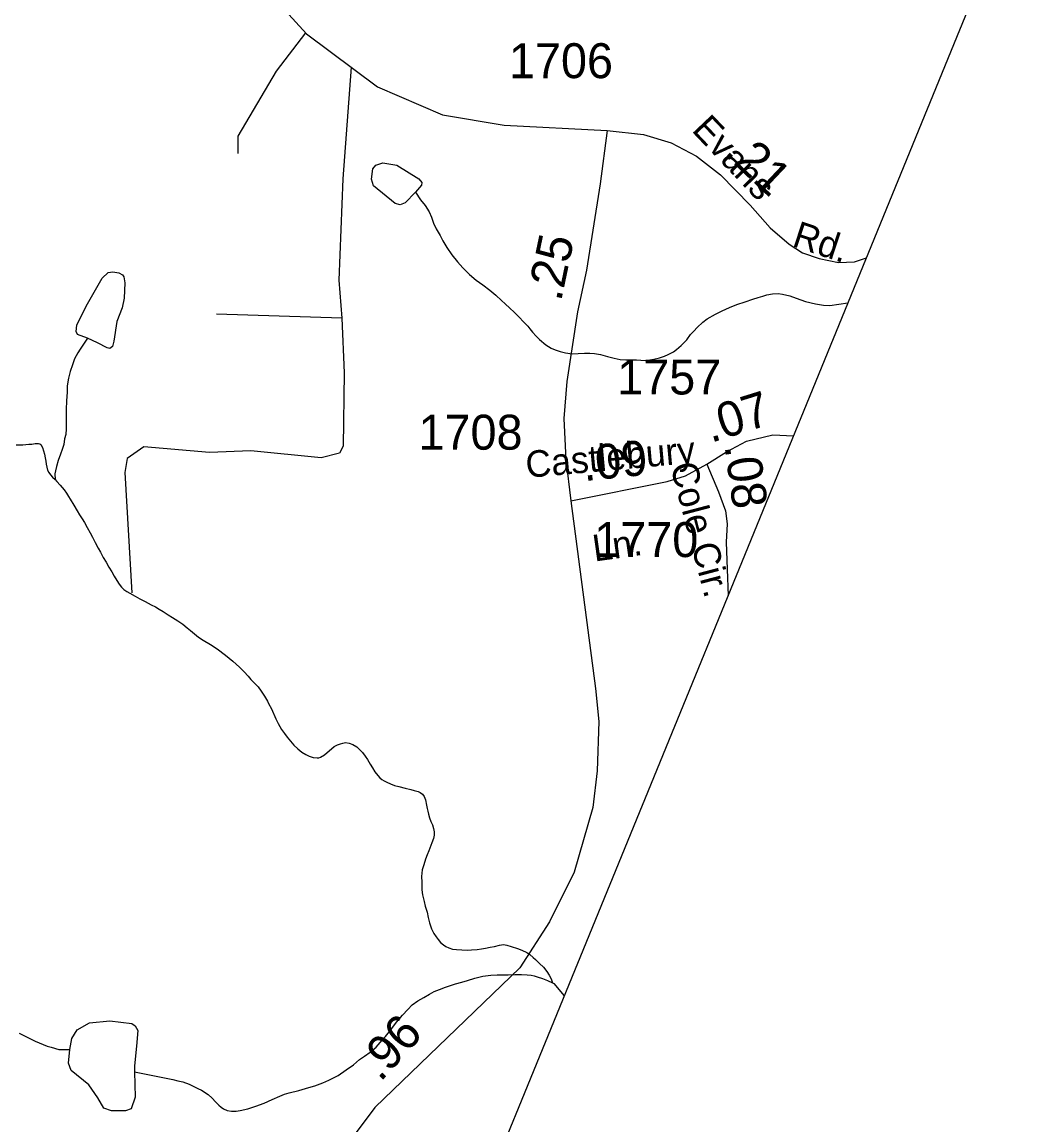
# Model space of a CAD drawing. Extents: x 2056842 to 2160602, y 826753 to 1016856.
# Drawn here: x 2136734 to 2140314, y 858350 to 862292 of the extents above; entities that cross this region are included whole.
import ezdxf

# ---------------------------------------------------------------- set-up
doc = ezdxf.new("R2010")
doc.units = 0
for name, color, linetype in [('Exist Boundary Political CountyLine', 7, 'Continuous'), ('Exist Hydrographic Misc Water Feature', 7, 'Continuous'), ('Exist Road Non-System Type 51', 7, 'Continuous'), ('Exist Road Non-System Type 51 Label', 7, 'Continuous'), ('Exist Road Secondary Mileage Hundredths English Label', 7, 'Continuous'), ('Exist Road Secondary Type 51 Attributed', 7, 'Continuous'), ('Exist Road Secondary Type 51 Label', 7, 'Continuous'), ('Exist Road Secondary Type 51 Number Label', 7, 'Continuous')]:
    doc.layers.add(name, color=color, linetype=linetype)

msp = doc.modelspace()

# ---------------------------------------------------------------- linework, layer by layer
at = {"layer": 'Exist Boundary Political CountyLine'}
msp.add_lwpolyline([(2133839.4, 827270.1), (2134339.4, 835334.3), (2134341.8, 841203.1), (2134508, 848637.7), (2140998.3, 864497.6)], dxfattribs=at)
at = {"layer": 'Exist Hydrographic Misc Water Feature'}
for points in [[(2138139.2, 861683.7), (2138102.5, 861646.3), (2138084.3, 861639), (2138067.3, 861643.9), (2137989.5, 861705.9), (2137982.2, 861730.3), (2137987, 861766.7), (2137998, 861780.1), (2138023.5, 861788.6), (2138073.3, 861780.1), (2138151.1, 861731.5), (2138162.1, 861718.1), (2138160.9, 861708.4), (2138139.2, 861683.7)], [(2138139.2, 861683.7), (2138157.8, 861657), (2138174.7, 861636.1), (2138188.6, 861613.8), (2138196.8, 861593.9), (2138204.4, 861573.3), (2138213.2, 861552.6), (2138227.4, 861528.5), (2138237.6, 861510.2), (2138252, 861486.1), (2138269.8, 861460.4), (2138290.3, 861434.5), (2138308.3, 861412.8), (2138332.5, 861389.3), (2138356.9, 861369.2), (2138380.1, 861352.2), (2138405.1, 861333.7), (2138426.9, 861315.1), (2138446.6, 861296.8), (2138459.5, 861284.2), (2138477.1, 861269.1), (2138491.9, 861254.8), (2138509.9, 861237.2), (2138525.7, 861220.5), (2138540.5, 861205.4), (2138548.5, 861195.5), (2138558.3, 861182.9), (2138570.4, 861169.5), (2138582.7, 861157.8), (2138604.9, 861137.7), (2138624.9, 861125.8), (2138638.9, 861119.7), (2138657.1, 861114.4), (2138675.2, 861110), (2138699.2, 861106.2), (2138721.1, 861106.6), (2138743.1, 861108.5), (2138763.2, 861108.9), (2138779.1, 861107), (2138801.1, 861103.2), (2138826.1, 861096.2), (2138849.1, 861090), (2138871.2, 861086.2), (2138891.1, 861084.1), (2138907.3, 861084.6), (2138929, 861084.1), (2138945.4, 861083), (2138961, 861082.7), (2138977, 861084.9), (2138991.2, 861087), (2139011.1, 861091.5), (2139029.1, 861097.7), (2139042.8, 861103.1), (2139061.1, 861113.5), (2139072.8, 861121.4), (2139088.8, 861135.8), (2139108.7, 861155.9), (2139122.8, 861174.5), (2139134.3, 861187.4), (2139146.4, 861200.3), (2139165.9, 861218.6), (2139181.9, 861230.6), (2139211.8, 861247.4), (2139235.6, 861259.1), (2139261.6, 861271.7), (2139287.5, 861281.8), (2139317.4, 861291.9), (2139344.9, 861301.2), (2139364.2, 861307.3), (2139381.2, 861312.7), (2139395.1, 861316.6), (2139415.2, 861320.1), (2139435.1, 861321.5), (2139451.1, 861319.4), (2139477.1, 861313.2), (2139500.5, 861304.5), (2139533.1, 861293.2), (2139569.4, 861284.2), (2139597.3, 861280.4), (2139619.7, 861279), (2139684.9, 861288.1)], [(2136967.3, 861161.6), (2136931.8, 861174.5), (2136927, 861185.4), (2136929.4, 861208.5), (2136962.2, 861276.6), (2137020.5, 861376.4), (2137041.2, 861397), (2137058.2, 861399.5), (2137080.1, 861395.8), (2137092.3, 861388.5), (2137097.1, 861381.2), (2137100.8, 861359.3), (2137098.3, 861304.6), (2137091, 861270.6), (2137072.8, 861221.9), (2137061.9, 861151.4), (2137057, 861131.9), (2137047.3, 861124.6), (2137037.6, 861127), (2137003.5, 861145.3), (2136967.3, 861161.6)], [(2136967.3, 861161.6), (2136941.1, 861122.8), (2136933.5, 861109), (2136921.4, 861088.7), (2136913.8, 861066.8), (2136905.8, 861042.3), (2136900, 861018.6), (2136895.1, 860991.7), (2136894.7, 860968.8), (2136892.9, 860938.4), (2136891.2, 860906.5), (2136891.4, 860876.1), (2136891.6, 860854), (2136891.6, 860838.4), (2136889.8, 860818), (2136885.9, 860802.5), (2136882.4, 860782), (2136876.5, 860764), (2136870.9, 860746.9), (2136862.9, 860724.2), (2136857, 860703.8), (2136853.1, 860688.3), (2136851, 860677.6), (2136851.5, 860656.3)], [(2136712.4, 860780.6), (2136736.4, 860780.9), (2136758.4, 860782.9), (2136768.4, 860783.5), (2136780.1, 860785), (2136788.1, 860785.6), (2136792.2, 860785.5), (2136797.3, 860784.6), (2136801.2, 860782), (2136806.3, 860771.2), (2136810.4, 860759.7), (2136813.3, 860747.3), (2136816.4, 860734.1), (2136818.6, 860721.8), (2136820.1, 860712), (2136822.3, 860700.4), (2136825.2, 860689.7), (2136829.1, 860681.4), (2136835, 860673.9), (2136843, 860665.5), (2136851.5, 860656.3)], [(2136851.5, 860656.3), (2136857.4, 860649.6), (2136869.3, 860636.3), (2136883.6, 860620.4), (2136893.1, 860607.9), (2136899.8, 860596.2), (2136905.8, 860586.4), (2136918.3, 860565.6), (2136930.4, 860544.7), (2136939.2, 860530.6), (2136948.4, 860516.5), (2136956.6, 860503.2), (2136966.9, 860485), (2136977.1, 860466.7), (2136985.1, 860450.9), (2136995.2, 860431.9), (2137006.1, 860411.2), (2137013.6, 860397.1), (2137024.1, 860377.9), (2137033.9, 860361.4), (2137044.2, 860344), (2137054, 860327.3), (2137062.4, 860311.6), (2137072.7, 860295.8), (2137080.7, 860282.5), (2137089.1, 860271.6), (2137097.7, 860263.3), (2137108, 860256.5), (2137119, 860250.5), (2137137.3, 860240.3), (2137155.1, 860230.1), (2137173.2, 860220.7), (2137195.1, 860208.8), (2137210.3, 860201.1), (2137223.4, 860193.4), (2137237.4, 860185), (2137255.6, 860173.1), (2137271.6, 860163.7), (2137289.9, 860151.9), (2137307.9, 860139.3), (2137323.7, 860126.5), (2137336.2, 860116.5), (2137349.7, 860104.7), (2137364.7, 860092.9), (2137380.3, 860082.7), (2137406.7, 860066.6), (2137430.7, 860051.3), (2137460.9, 860029.4), (2137486.9, 860007.5), (2137511.1, 859985.7), (2137527.3, 859969.8), (2137541.5, 859953.9), (2137551.7, 859942.2), (2137563.6, 859930.5), (2137576.9, 859915.4), (2137587.8, 859900.5), (2137599.9, 859882.2), (2137610.3, 859864.7), (2137614, 859856.4), (2137624.7, 859836.5), (2137640.9, 859801), (2137648.9, 859785.2), (2137661.2, 859762.8), (2137671.5, 859749.4), (2137681.3, 859735.2), (2137693.4, 859721.1), (2137705.3, 859706.9), (2137719.6, 859693.5), (2137733.8, 859681.7), (2137748.1, 859674), (2137760, 859668.1), (2137774.2, 859663.6), (2137787.9, 859661.7), (2137794.3, 859662.4), (2137799.8, 859663.9), (2137814, 859672.7), (2137823.8, 859680.7), (2137839.6, 859694.3), (2137849.6, 859702.3), (2137861.5, 859708.6), (2137871.4, 859712.5), (2137879.6, 859714.8), (2137890, 859717.1), (2137903.2, 859714.3), (2137916.1, 859709.2), (2137929.6, 859701.5), (2137940.1, 859691.4), (2137949.9, 859681.3), (2137960.2, 859668), (2137968.2, 859655.5), (2137977.8, 859639.8), (2137985.8, 859625.6), (2137994.4, 859611.6), (2138004.9, 859598.2), (2138011.8, 859590.6), (2138019.2, 859584.8), (2138027.2, 859579.7), (2138036.9, 859574.6), (2138050.2, 859568.5), (2138064.1, 859563.4)], [(2138064.1, 859563.4), (2138079.9, 859558.9), (2138102.7, 859553.5), (2138123.2, 859549), (2138134.9, 859545.5), (2138149.2, 859541.1), (2138156.8, 859537.6), (2138165.2, 859531.7), (2138171.2, 859523.4), (2138174.9, 859511.8), (2138179.2, 859492.9), (2138181.6, 859481.3), (2138183.7, 859471.5), (2138186.1, 859460.8), (2138189.6, 859447.6), (2138195, 859434.3), (2138200.1, 859421.9), (2138204.2, 859409.5), (2138206.8, 859397.2), (2138206.4, 859385.7), (2138204.2, 859373.5), (2138198.6, 859358), (2138194.5, 859349), (2138190.9, 859339.3), (2138187, 859329.6), (2138181.2, 859315.7), (2138175.1, 859299.4), (2138169.3, 859279.8), (2138163.6, 859261.1), (2138161.5, 859237.3), (2138161.9, 859217.6), (2138162.1, 859205.3), (2138162.1, 859189.8), (2138164.4, 859171.7), (2138170.3, 859147.8), (2138174.7, 859131.3), (2138180.8, 859109.8), (2138184.9, 859091.7), (2138189.6, 859072.7), (2138196.8, 859050.4), (2138205.6, 859033.8), (2138213.2, 859022.2), (2138220.4, 859012.2), (2138229.2, 859002.2), (2138239.9, 858993.8), (2138247.9, 858987.8), (2138258.7, 858982.7), (2138271.8, 858978.4), (2138286.2, 858976.4), (2138305.7, 858975.2), (2138323.9, 858974.8), (2138339.9, 858975.3), (2138360.2, 858977.3), (2138375.4, 858978.7), (2138390, 858981.6), (2138406.4, 858984.6), (2138421.9, 858987.5), (2138439.6, 858992.1), (2138453.9, 858994.3), (2138465.8, 858992.4), (2138481.8, 858988), (2138504, 858980.1), (2138519.1, 858974), (2138537.4, 858965.5), (2138548.1, 858958.7), (2138560.2, 858948.6), (2138568.4, 858941), (2138583.1, 858926.8), (2138596.6, 858913.4), (2138608.5, 858897.6), (2138616.9, 858885.1), (2138624.9, 858871.8), (2138629.8, 858857.1), (2138634, 858855.2)], [(2137135.4, 858539.1), (2137272.4, 858511.8), (2137290.7, 858507.3), (2137308.3, 858503.7), (2137330.5, 858495.8), (2137362.4, 858480.4), (2137374.5, 858474.4), (2137398.5, 858458.3), (2137412.9, 858445), (2137425.2, 858432.4), (2137437.1, 858420.6), (2137445.1, 858413.1), (2137453.1, 858407.2), (2137466.6, 858401.1), (2137481.6, 858398.4), (2137498.8, 858398.8), (2137513.2, 858401.8), (2137541, 858407.8), (2137569.1, 858416.3), (2137598.7, 858427.1), (2137627, 858440.5), (2137654.6, 858453.1), (2137671.5, 858460.1), (2137688.7, 858464.6), (2137722.7, 858472.9), (2137758.4, 858483.7), (2137780.3, 858489.8), (2137808.2, 858499.9), (2137830.2, 858509.2), (2137849, 858518.8), (2137863.8, 858526.6), (2137891.9, 858546.6), (2137917.7, 858564.9), (2137939.7, 858583.3), (2137957.3, 858595.3), (2137977.2, 858609.6), (2137999.1, 858628), (2138020.9, 858652.2), (2138032.6, 858665.9), (2138054.7, 858694.1), (2138072.3, 858716.7), (2138093.5, 858742.5), (2138111.9, 858762.6), (2138128.3, 858779.5), (2138147.6, 858793.1), (2138169.5, 858805.8), (2138189.4, 858817.6), (2138206, 858826.4), (2138225.3, 858834.1), (2138247, 858841.9), (2138283.1, 858854.3), (2138304.9, 858860.4), (2138325, 858866.5), (2138352.2, 858874.1), (2138379.9, 858881), (2138408.4, 858884.5), (2138431.2, 858886.5), (2138450.9, 858886.1), (2138471, 858886.5), (2138494.9, 858887.6), (2138518.5, 858887.2), (2138538.8, 858886.7), (2138552.4, 858885.6), (2138563.8, 858882.9), (2138574.9, 858879.4), (2138593, 858873.3), (2138611.8, 858865.5), (2138629.8, 858857.1), (2138634, 858855.2)], [(2138634, 858855.2), (2138671.5, 858811.7)], [(2136904.5, 858619.4), (2136911.8, 858658.3), (2136931.2, 858689.9), (2136975, 858714.2), (2137047.9, 858721.5), (2137125.7, 858711.8), (2137137.8, 858704.5), (2137147.6, 858687.5), (2137142.7, 858631.5), (2137135.4, 858561), (2137135.4, 858539.1)], [(2136722.9, 858678.2), (2136735, 858672.2), (2136749.1, 858664.5), (2136781.1, 858649), (2136795.1, 858643), (2136809.2, 858637), (2136823.2, 858631), (2136837.3, 858627.5), (2136865.4, 858619.4), (2136904.5, 858619.4)], [(2137135.4, 858539.1), (2137137.8, 858449.1), (2137123.2, 858407.7), (2137103.8, 858400.5), (2137052.8, 858400.5), (2137026, 858410.2), (2137004.1, 858446.7), (2136972.5, 858492.9), (2136909.3, 858544), (2136899.6, 858570.7), (2136904.5, 858619.4)]]:
    msp.add_lwpolyline(points, dxfattribs=at)
at = {"layer": 'Exist Road Non-System Type 51'}
msp.add_line((2137876.9, 861233.4), (2137428.3, 861248), dxfattribs=at)
for points in [[(2137746.3, 862252.8), (2137642.2, 862116.7), (2137505.2, 861884), (2137505.2, 861821.6)], [(2137910, 862130.7), (2137880.1, 861731.2), (2137865.5, 861369.5), (2137876.9, 861233.4)], [(2137876.9, 861233.4), (2137885.3, 861038), (2137881.1, 860776.2), (2137868.6, 860751.2), (2137802.2, 860734.6), (2137550.9, 860759.5), (2137403.4, 860753.3), (2137168.7, 860774.1), (2137109.5, 860731.5), (2137101.2, 860681.6), (2137126.1, 860251.3)]]:
    msp.add_lwpolyline(points, dxfattribs=at)
at = {"layer": 'Exist Road Secondary Type 51 Attributed'}
for points in [[(2136759.9, 863029), (2136829.9, 863007.3), (2136898.8, 862977.1), (2137148.9, 862874.4), (2137287.6, 862819.3), (2137387.4, 862721.4), (2137471, 862607.3), (2137585, 862432.3), (2137750.3, 862249.8), (2138004, 862060.6), (2138235.8, 861959.8), (2138456.3, 861923.7), (2138824.8, 861904.1)], [(2138824.8, 861904.1), (2138799.2, 861713.1), (2138750.7, 861405.1), (2138718.2, 861256.1), (2138680.9, 861007.3), (2138669.3, 860874.5), (2138676.3, 860727.8), (2138694.9, 860581)], [(2138824.8, 861904.1), (2138954.1, 861889.4), (2139052.9, 861859.8), (2139143.7, 861812.1), (2139229.8, 861745.7), (2139335.3, 861637.7), (2139407.5, 861556.2), (2139475, 861498), (2139522.7, 861466.5), (2139582.1, 861446.7), (2139651.7, 861431.9), (2139708.4, 861435.3), (2139751, 861449.7)], [(2139181.3, 860711.5), (2139251.2, 860755.7), (2139322.2, 860793.8), (2139416.4, 860816.3), (2139490.5, 860813.2)], [(2138694.9, 860581), (2139038.8, 860649.9), (2139104.5, 860670.3), (2139181.3, 860711.5)], [(2139181.3, 860711.5), (2139222.3, 860612.4), (2139246.9, 860545.2), (2139253.4, 860497.8), (2139250.1, 860432.3), (2139253.4, 860335.7), (2139256.4, 860241.1)], [(2138694.9, 860581), (2138783.1, 859909.9), (2138794.5, 859792), (2138788.8, 859615.2), (2138773.6, 859484), (2138706.2, 859253), (2138618.7, 859076.1), (2138512.3, 858910.7), (2137994.5, 858411.5), (2137825.4, 858185.2), (2137594.5, 857739.3), (2137548.9, 857539.7), (2137533.7, 857374.2), (2137479, 855897.8)]]:
    msp.add_lwpolyline(points, dxfattribs=at)

# ---------------------------------------------------------------- texts
at = {"layer": 'Exist Road Non-System Type 51 Label'}
msp.add_text('Cole Cir.', height=95, rotation=284.7312, dxfattribs=at).set_placement((2139049.4, 860706))
at = {"layer": 'Exist Road Secondary Mileage Hundredths English Label'}
for s, rotation, p in [('.21', 316.676, (2139238.4, 861821.2)), ('.25', 78.2108, (2138659.6, 861290.2)), ('.07', 17.3288, (2139195.1, 860787.4)), ('.09', 5.9241, (2138742.1, 860650.6)), ('.08', 277.8128, (2139243.7, 860776.6)), ('.96', 47.7648, (2138014.1, 858500.7))]:
    msp.add_text(s, height=125, rotation=rotation, dxfattribs=at).set_placement(p)
at = {"layer": 'Exist Road Secondary Type 51 Label'}
for s, rotation, p in [('Evans', 313.4708, (2139123.6, 861903.8)), ('Rd.', 341.7137, (2139481.5, 861491.9)), ('Castlebury', 5.1432, (2138537.3, 860662.5)), ('Ln.', 7.9837, (2138779.3, 860363.3))]:
    msp.add_text(s, height=95, rotation=rotation, dxfattribs=at).set_placement(p)
at = {"layer": 'Exist Road Secondary Type 51 Number Label'}
for s, p in [('1706', (2138473.6, 862091.3)), ('1757', (2138860.3, 860960.7)), ('1708', (2138150.3, 860763.4)), ('1770', (2138778.4, 860379.6))]:
    msp.add_text(s, height=125, dxfattribs=at).set_placement(p)

doc.saveas('drawing.dxf')
